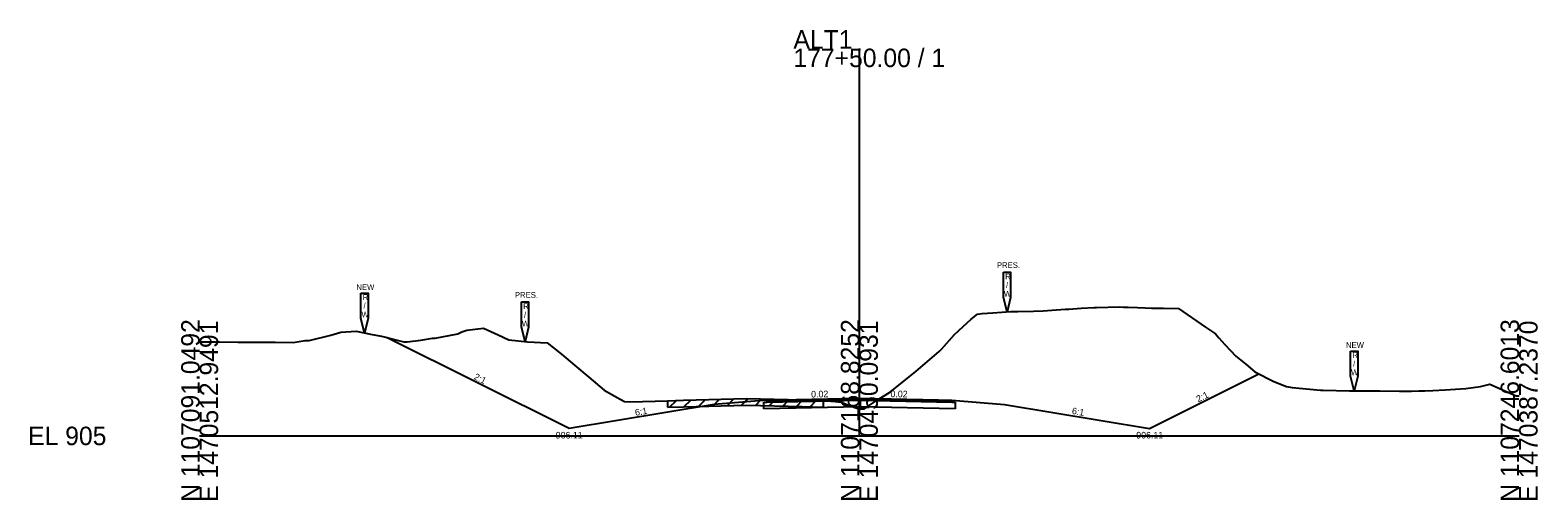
# Model space of a CAD drawing. Extents: x -26 to 2203, y -10 to 19568.
# Drawn here: x 974.3 to 1202.8, y 19490.3 to 19561.5 of the extents above; entities that cross this region are included whole.
import ezdxf

# ---------------------------------------------------------------- set-up
doc = ezdxf.new("R2010")
doc.units = 0
for name, color, linetype in [('RD_GPK_XS_Cell', 7, 'Continuous'), ('RD_XS_Base', 7, 'Continuous'), ('RD_XS_ExGround', 7, 'Continuous'), ('RD_XS_ExPaveRet', 7, 'Continuous'), ('RD_XS_ExRW', 7, 'Continuous'), ('RD_XS_Greenside', 7, 'Continuous'), ('RD_XS_NewRW', 7, 'Continuous'), ('RD_XS_Pave', 7, 'Continuous'), ('RD_XS_TieSlope', 7, 'Continuous'), ('RD_XS_TX_Slope', 7, 'Continuous')]:
    doc.layers.add(name, color=color, linetype=linetype)

msp = doc.modelspace()

# ---------------------------------------------------------------- linework, layer by layer
at = {"layer": 'RD_GPK_XS_Cell'}
for p, q in [((1100, 19500), (1100, 19558.71)), ((1000, 19500), (1100, 19500)), ((1100, 19500), (1200, 19500))]:
    msp.add_line(p, q, dxfattribs=at)
at = {"layer": 'RD_XS_Base'}
for points in [[(1085.5, 19505.11), (1086, 19505.12), (1100, 19505.4), (1114, 19505.12), (1114.5, 19505.11)], [(1085.5, 19504.11), (1085.5, 19505.11)], [(1114.5, 19504.11), (1100, 19504.4), (1085.5, 19504.11)], [(1114.5, 19505.11), (1114.5, 19504.11)]]:
    msp.add_lwpolyline(points, dxfattribs=at)
at = {"layer": 'RD_XS_ExGround'}
msp.add_lwpolyline([(1000, 19514.28), (1001.95, 19514.26), (1003, 19514.24), (1005.81, 19514.22), (1009.44, 19514.2), (1011.43, 19514.22), (1014.15, 19514.17), (1016.01, 19514.44), (1016.62, 19514.47), (1019.87, 19515.25), (1021.4, 19515.71), (1023.72, 19515.89), (1026.17, 19515.37), (1027.58, 19515.13), (1030.94, 19514.27), (1031.44, 19514.24), (1033.52, 19514.51), (1035.29, 19514.8), (1035.72, 19514.81), (1039.15, 19515.48), (1039.75, 19515.77), (1040.49, 19516.04), (1043.01, 19516.31), (1045.26, 19515.32), (1046.87, 19514.54), (1048.28, 19514.41), (1049.69, 19514.26), (1052.7, 19514.09), (1054.84, 19512.39), (1056.81, 19510.74), (1058.97, 19508.92), (1061.31, 19506.91), (1063.76, 19505.55), (1064.39, 19505.2), (1065.19, 19505.18), (1069.06, 19505.29), (1070.93, 19505.34), (1073.33, 19505.41), (1082.88, 19505.66), (1091.34, 19505.46), (1094.52, 19505.37), (1096.33, 19505.22), (1097.25, 19505.11), (1099.31, 19504.33), (1099.92, 19504.1), (1100.66, 19504.1), (1101.33, 19504.51), (1102.86, 19505.52), (1104.72, 19506.66), (1107.31, 19508.74), (1108.58, 19509.78), (1112.08, 19512.81), (1112.44, 19513.16), (1114.41, 19515.37), (1116.92, 19517.69), (1117.89, 19518.44), (1118.63, 19518.56), (1120.23, 19518.64), (1122.94, 19518.86), (1124.01, 19518.88), (1126.4, 19518.92), (1127.87, 19518.95), (1131.17, 19519.2), (1131.73, 19519.23), (1133.61, 19519.35), (1135.58, 19519.47), (1135.94, 19519.49), (1139.44, 19519.57), (1140.01, 19519.54), (1140.72, 19519.52), (1142.14, 19519.49), (1143.3, 19519.43), (1144.28, 19519.38), (1146.12, 19519.37), (1148.39, 19519.3), (1152.48, 19516.51), (1153.97, 19515.47), (1154.49, 19514.86), (1155.38, 19513.87), (1157.08, 19512.11), (1158.56, 19510.89), (1159.95, 19509.7), (1162.8, 19508.27), (1164.73, 19507.47), (1165.6, 19507.35), (1168.28, 19507.11), (1169.88, 19506.95), (1170.3, 19506.92), (1174.27, 19506.85), (1178.01, 19506.85), (1178.9, 19506.85), (1181.87, 19506.78), (1183.67, 19506.79), (1184.81, 19506.81), (1185.73, 19506.84), (1186.94, 19506.87), (1188.78, 19507), (1191.94, 19507.17), (1194.15, 19507.47), (1195.55, 19507.82), (1199.09, 19506.29), (1199.54, 19506.09), (1200, 19506.06)], dxfattribs=at)
at = {"layer": 'RD_XS_ExPaveRet'}
for p, q in [((1070.93, 19505.34), (1070.93, 19504.34)), ((1071.23, 19504.35), (1072.26, 19505.38)), ((1073.41, 19504.41), (1074.44, 19505.44)), ((1075.59, 19504.47), (1076.62, 19505.49)), ((1077.77, 19504.52), (1078.79, 19505.55)), ((1079.95, 19504.58), (1080.97, 19505.61)), ((1082.13, 19504.64), (1083.14, 19505.65)), ((1084.23, 19504.63), (1085.21, 19505.6)), ((1086.31, 19504.58), (1087.28, 19505.55)), ((1088.38, 19504.53), (1089.35, 19505.5)), ((1090.45, 19504.48), (1091.43, 19505.45)), ((1092.52, 19504.42), (1093.49, 19505.4)), ((1094.52, 19505.37), (1094.52, 19504.37))]:
    msp.add_line(p, q, dxfattribs=at)
msp.add_lwpolyline([(1070.93, 19504.34), (1073.35, 19504.41), (1082.88, 19504.66), (1091.31, 19504.46), (1094.52, 19504.37)], dxfattribs=at)
at = {"layer": 'RD_XS_ExRW'}
for points in [[(1121.84, 19524.82), (1122.93, 19524.82), (1122.93, 19520.99), (1122.39, 19518.81), (1121.84, 19520.99)], [(1048.78, 19520.31), (1049.87, 19520.31), (1049.87, 19516.48), (1049.32, 19514.29), (1048.78, 19516.48)]]:
    msp.add_lwpolyline(points, close=True, dxfattribs=at)
at = {"layer": 'RD_XS_Greenside'}
for points in [[(1086, 19505.44), (1078, 19504.77)], [(1114, 19505.44), (1122, 19504.77)], [(1078, 19504.77), (1056, 19501.11)], [(1122, 19504.77), (1144, 19501.11)]]:
    msp.add_lwpolyline(points, dxfattribs=at)
at = {"layer": 'RD_XS_NewRW'}
for points in [[(1024.45, 19521.63), (1025.55, 19521.63), (1025.55, 19517.81), (1025, 19515.62), (1024.45, 19517.81)], [(1174.45, 19512.87), (1175.55, 19512.87), (1175.55, 19509.04), (1175, 19506.85), (1174.45, 19509.04)]]:
    msp.add_lwpolyline(points, close=True, dxfattribs=at)
at = {"layer": 'RD_XS_Pave'}
for points in [[(1086, 19505.44), (1088, 19505.48), (1100, 19505.72), (1112, 19505.48), (1114, 19505.44)], [(1086, 19505.28), (1100, 19505.56), (1114, 19505.28)], [(1114, 19505.28), (1100, 19505.56), (1086, 19505.28)], [(1086, 19505.28), (1086, 19505.44)], [(1114, 19505.12), (1100, 19505.4), (1086, 19505.12)], [(1086, 19505.12), (1086, 19505.28)], [(1114, 19505.44), (1114, 19505.28)], [(1114, 19505.28), (1114, 19505.12)]]:
    msp.add_lwpolyline(points, dxfattribs=at)
at = {"layer": 'RD_XS_TieSlope'}
for points in [[(1056, 19501.11), (1028.33, 19514.94)], [(1144, 19501.11), (1160.57, 19509.39)]]:
    msp.add_lwpolyline(points, dxfattribs=at)

# ---------------------------------------------------------------- texts
at = {"layer": 'RD_GPK_XS_Cell'}
for s, p in [('ALT1', (1090, 19558.71)), ('177+50.00 / 1', (1090, 19555.91)), ('EL 905', (974, 19498.6))]:
    msp.add_text(s, height=2.8, dxfattribs=at).set_placement(p)
for s, p in [('N 1107091.0492', (1000, 19490)), ('E 1470512.9491', (1002.8, 19490)), ('N 1107168.8252', (1100, 19490)), ('E 1470450.0931', (1102.8, 19490)), ('N 1107246.6013', (1200, 19490)), ('E 1470387.2370', (1202.8, 19490))]:
    msp.add_text(s, height=2.8, rotation=90, dxfattribs=at).set_placement(p)
at = {"layer": 'RD_XS_ExRW'}
for s, p in [('PRES.', (1120.84, 19525.45)), ('R', (1122.1, 19523.73)), ('PRES.', (1047.78, 19520.94)), ('W', (1121.91, 19521.11)), ('/', (1122.22, 19522.42)), ('R', (1049.04, 19519.22)), ('W', (1048.85, 19516.59)), ('/', (1049.16, 19517.91))]:
    msp.add_text(s, height=0.875, dxfattribs=at).set_placement(p)
at = {"layer": 'RD_XS_NewRW'}
for s, p in [('NEW', (1023.75, 19522.12)), ('R', (1024.71, 19520.6)), ('/', (1024.83, 19519.28)), ('W', (1024.53, 19517.97)), ('NEW', (1173.75, 19513.35)), ('R', (1174.71, 19511.83)), ('W', (1174.53, 19509.2)), ('/', (1174.83, 19510.51))]:
    msp.add_text(s, height=0.875, dxfattribs=at).set_placement(p)
at = {"layer": 'RD_XS_TX_Slope'}
for s, rotation, p in [('2:1', 333.4349, (1041.47, 19508.65)), ('0.02', 1.1458, (1092.69, 19505.82)), ('0.02', 358.8542, (1104.7, 19505.88)), ('2:1', 26.5651, (1151.37, 19505.07)), ('6:1', 9.4642, (1066.07, 19503.04)), ('6:1', 350.5358, (1132.16, 19503.33))]:
    msp.add_text(s, height=1, rotation=rotation, dxfattribs=at).set_placement(p)
for p in [(1053.97, 19499.61), (1141.97, 19499.61)]:
    msp.add_text('906.11', height=1, dxfattribs=at).set_placement(p)

doc.saveas('drawing.dxf')
